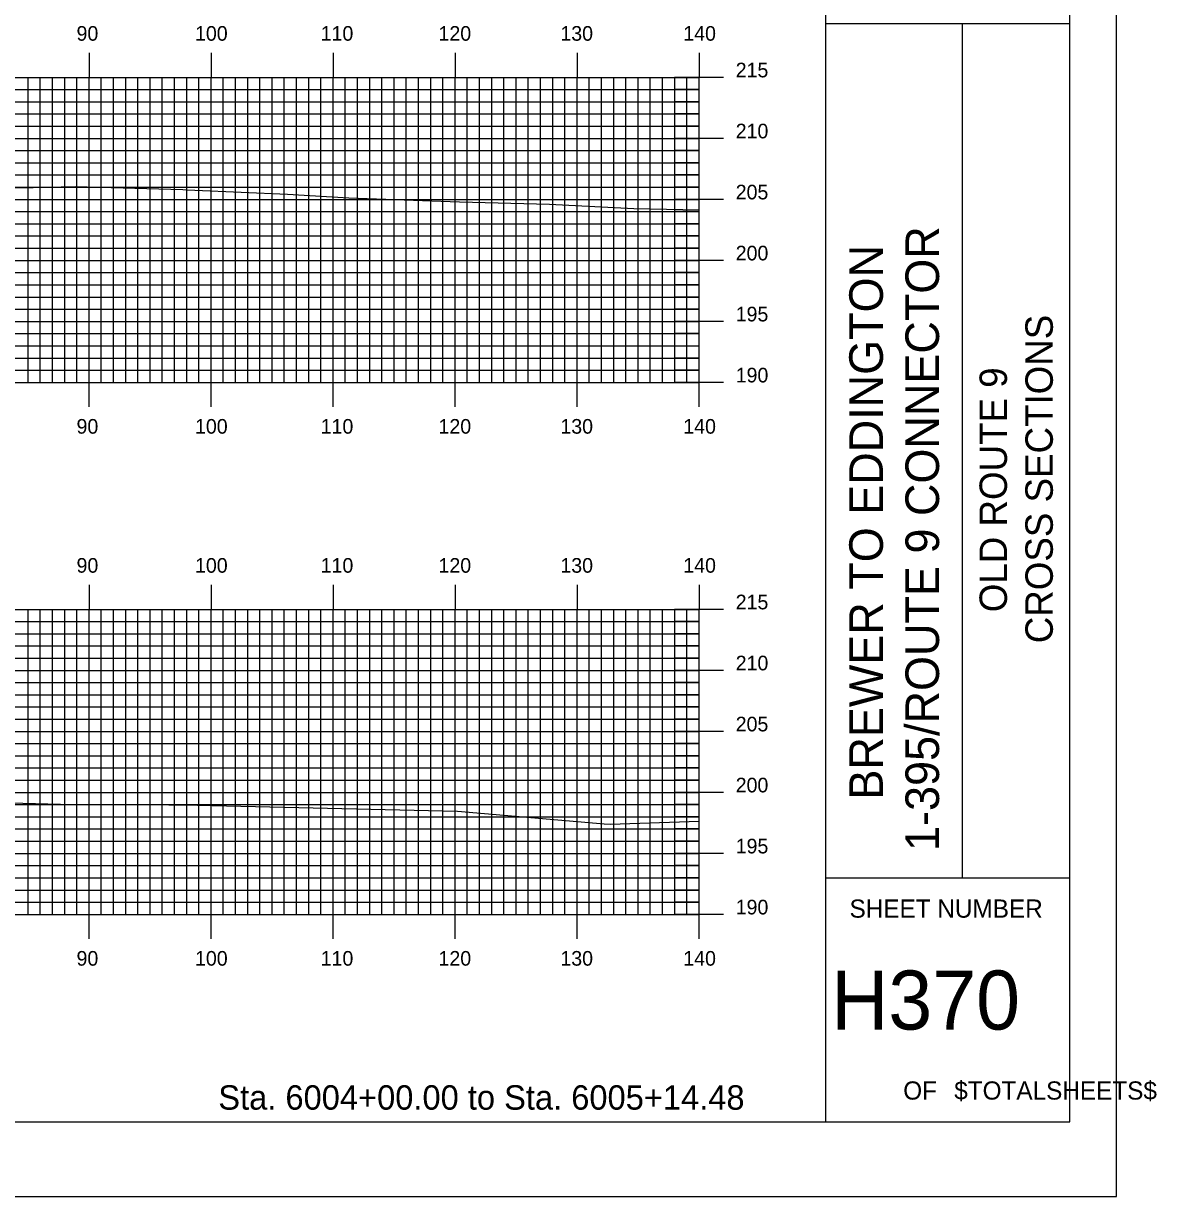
# Model space of a CAD drawing. Extents: x 852087 to 852430, y 366898 to 367118.
# Drawn here: x 852337.2 to 852430, y 366898.4 to 366994.5 of the extents above; entities that cross this region are included whole.
import ezdxf

# ---------------------------------------------------------------- set-up
doc = ezdxf.new("R2010")
doc.units = 0
for name, color, linetype in [('BORDER', 7, 'Continuous'), ('H_V ANNOTATION', 7, 'Continuous'), ('MAJOR', 7, 'Continuous'), ('MINOR', 7, 'Continuous'), ('PLOT BOUNDARY', 7, 'Continuous'), ('S_Roadway_Centerline', 7, 'Continuous')]:
    doc.layers.add(name, color=color, linetype=linetype)

msp = doc.modelspace()

# ---------------------------------------------------------------- linework, layer by layer
at = {"layer": 'BORDER'}
for p, q in [((852402.931, 366904.473), (852402.931, 367114.473)), ((852402.931, 366994.479), (852422.931, 366994.479)), ((852414.113, 366924.479), (852414.113, 366994.479)), ((852402.931, 366924.479), (852422.931, 366924.479))]:
    msp.add_line(p, q, dxfattribs=at)
msp.add_lwpolyline([(852102.931, 366904.473), (852422.931, 366904.473), (852422.931, 367114.473), (852102.931, 367114.473)], close=True, dxfattribs=at)
at = {"layer": 'MAJOR'}
for p, q in [((852342.531, 366992.071), (852342.531, 366990.067)), ((852352.531, 366992.071), (852352.531, 366990.067)), ((852362.531, 366992.071), (852362.531, 366990.067)), ((852372.531, 366992.071), (852372.531, 366990.067)), ((852382.531, 366992.071), (852382.531, 366990.067)), ((852392.531, 366992.071), (852392.531, 366990.067)), ((852112.531, 366990.067), (852392.531, 366990.067)), ((852112.531, 366990.067), (852392.531, 366990.067)), ((852342.531, 366965.067), (852342.531, 366990.067)), ((852352.531, 366965.067), (852352.531, 366990.067)), ((852362.531, 366965.067), (852362.531, 366990.067)), ((852372.531, 366965.067), (852372.531, 366990.067)), ((852382.531, 366965.067), (852382.531, 366990.067)), ((852394.535, 366990.067), (852390.527, 366990.067)), ((852392.531, 366965.067), (852392.531, 366990.067)), ((852392.531, 366965.067), (852392.531, 366990.067)), ((852112.531, 366985.067), (852392.531, 366985.067)), ((852394.535, 366985.067), (852390.527, 366985.067)), ((852112.531, 366980.067), (852392.531, 366980.067)), ((852394.535, 366980.067), (852390.527, 366980.067)), ((852112.531, 366975.067), (852392.531, 366975.067)), ((852394.535, 366975.067), (852390.527, 366975.067)), ((852112.531, 366970.067), (852392.531, 366970.067)), ((852394.535, 366970.067), (852390.527, 366970.067)), ((852112.531, 366965.067), (852392.531, 366965.067)), ((852112.531, 366965.067), (852392.531, 366965.067)), ((852342.531, 366963.063), (852342.531, 366965.067)), ((852352.531, 366963.063), (852352.531, 366965.067)), ((852362.531, 366963.063), (852362.531, 366965.067)), ((852372.531, 366963.063), (852372.531, 366965.067)), ((852382.531, 366963.063), (852382.531, 366965.067)), ((852394.535, 366965.067), (852390.527, 366965.067)), ((852392.531, 366963.063), (852392.531, 366965.067)), ((852342.531, 366948.477), (852342.531, 366946.473)), ((852352.531, 366948.477), (852352.531, 366946.473)), ((852362.531, 366948.477), (852362.531, 366946.473)), ((852372.531, 366948.477), (852372.531, 366946.473)), ((852382.531, 366948.477), (852382.531, 366946.473)), ((852392.531, 366948.477), (852392.531, 366946.473)), ((852112.531, 366946.473), (852392.531, 366946.473)), ((852112.531, 366946.473), (852392.531, 366946.473)), ((852342.531, 366921.473), (852342.531, 366946.473)), ((852352.531, 366921.473), (852352.531, 366946.473)), ((852362.531, 366921.473), (852362.531, 366946.473)), ((852372.531, 366921.473), (852372.531, 366946.473)), ((852382.531, 366921.473), (852382.531, 366946.473)), ((852394.535, 366946.473), (852390.527, 366946.473)), ((852392.531, 366921.473), (852392.531, 366946.473)), ((852392.531, 366921.473), (852392.531, 366946.473)), ((852112.531, 366941.473), (852392.531, 366941.473)), ((852394.535, 366941.473), (852390.527, 366941.473)), ((852112.531, 366936.473), (852392.531, 366936.473)), ((852394.535, 366936.473), (852390.527, 366936.473)), ((852112.531, 366931.473), (852392.531, 366931.473)), ((852394.535, 366931.473), (852390.527, 366931.473)), ((852112.531, 366926.473), (852392.531, 366926.473)), ((852394.535, 366926.473), (852390.527, 366926.473)), ((852112.531, 366921.473), (852392.531, 366921.473)), ((852112.531, 366921.473), (852392.531, 366921.473)), ((852342.531, 366919.469), (852342.531, 366921.473)), ((852352.531, 366919.469), (852352.531, 366921.473)), ((852362.531, 366919.469), (852362.531, 366921.473)), ((852372.531, 366919.469), (852372.531, 366921.473)), ((852382.531, 366919.469), (852382.531, 366921.473)), ((852394.535, 366921.473), (852390.527, 366921.473)), ((852392.531, 366919.469), (852392.531, 366921.473))]:
    msp.add_line(p, q, dxfattribs=at)
at = {"layer": 'MINOR'}
for p, q in [((852337.531, 366965.067), (852337.531, 366990.067)), ((852338.531, 366965.067), (852338.531, 366990.067)), ((852339.531, 366965.067), (852339.531, 366990.067)), ((852340.531, 366965.067), (852340.531, 366990.067)), ((852341.531, 366965.067), (852341.531, 366990.067)), ((852343.531, 366965.067), (852343.531, 366990.067)), ((852344.531, 366965.067), (852344.531, 366990.067)), ((852345.531, 366965.067), (852345.531, 366990.067)), ((852346.531, 366965.067), (852346.531, 366990.067)), ((852347.531, 366965.067), (852347.531, 366990.067)), ((852348.531, 366965.067), (852348.531, 366990.067)), ((852349.531, 366965.067), (852349.531, 366990.067)), ((852350.531, 366965.067), (852350.531, 366990.067)), ((852351.531, 366965.067), (852351.531, 366990.067)), ((852353.531, 366965.067), (852353.531, 366990.067)), ((852354.531, 366965.067), (852354.531, 366990.067)), ((852355.531, 366965.067), (852355.531, 366990.067)), ((852356.531, 366965.067), (852356.531, 366990.067)), ((852357.531, 366965.067), (852357.531, 366990.067)), ((852358.531, 366965.067), (852358.531, 366990.067)), ((852359.531, 366965.067), (852359.531, 366990.067)), ((852360.531, 366965.067), (852360.531, 366990.067)), ((852361.531, 366965.067), (852361.531, 366990.067)), ((852363.531, 366965.067), (852363.531, 366990.067)), ((852364.531, 366965.067), (852364.531, 366990.067)), ((852365.531, 366965.067), (852365.531, 366990.067)), ((852366.531, 366965.067), (852366.531, 366990.067)), ((852367.531, 366965.067), (852367.531, 366990.067)), ((852368.531, 366965.067), (852368.531, 366990.067)), ((852369.531, 366965.067), (852369.531, 366990.067)), ((852370.531, 366965.067), (852370.531, 366990.067)), ((852371.531, 366965.067), (852371.531, 366990.067)), ((852373.531, 366965.067), (852373.531, 366990.067)), ((852374.531, 366965.067), (852374.531, 366990.067)), ((852375.531, 366965.067), (852375.531, 366990.067)), ((852376.531, 366965.067), (852376.531, 366990.067)), ((852377.531, 366965.067), (852377.531, 366990.067)), ((852378.531, 366965.067), (852378.531, 366990.067)), ((852379.531, 366965.067), (852379.531, 366990.067)), ((852380.531, 366965.067), (852380.531, 366990.067)), ((852381.531, 366965.067), (852381.531, 366990.067)), ((852383.531, 366965.067), (852383.531, 366990.067)), ((852384.531, 366965.067), (852384.531, 366990.067)), ((852385.531, 366965.067), (852385.531, 366990.067)), ((852386.531, 366965.067), (852386.531, 366990.067)), ((852387.531, 366965.067), (852387.531, 366990.067)), ((852388.531, 366965.067), (852388.531, 366990.067)), ((852389.531, 366965.067), (852389.531, 366990.067)), ((852390.531, 366965.067), (852390.531, 366990.067)), ((852391.531, 366965.067), (852391.531, 366990.067)), ((852112.531, 366989.067), (852392.531, 366989.067)), ((852392.531, 366989.067), (852390.527, 366989.067)), ((852112.531, 366988.067), (852392.531, 366988.067)), ((852392.531, 366988.067), (852390.527, 366988.067)), ((852112.531, 366987.067), (852392.531, 366987.067)), ((852392.531, 366987.067), (852390.527, 366987.067)), ((852112.531, 366986.067), (852392.531, 366986.067)), ((852392.531, 366986.067), (852390.527, 366986.067)), ((852112.531, 366984.067), (852392.531, 366984.067)), ((852392.531, 366984.067), (852390.527, 366984.067)), ((852112.531, 366983.067), (852392.531, 366983.067)), ((852392.531, 366983.067), (852390.527, 366983.067)), ((852112.531, 366982.067), (852392.531, 366982.067)), ((852392.531, 366982.067), (852390.527, 366982.067)), ((852112.531, 366981.067), (852392.531, 366981.067)), ((852392.531, 366981.067), (852390.527, 366981.067)), ((852112.531, 366979.067), (852392.531, 366979.067)), ((852392.531, 366979.067), (852390.527, 366979.067)), ((852112.531, 366978.067), (852392.531, 366978.067)), ((852392.531, 366978.067), (852390.527, 366978.067)), ((852112.531, 366977.067), (852392.531, 366977.067)), ((852392.531, 366977.067), (852390.527, 366977.067)), ((852112.531, 366976.067), (852392.531, 366976.067)), ((852392.531, 366976.067), (852390.527, 366976.067)), ((852112.531, 366974.067), (852392.531, 366974.067)), ((852392.531, 366974.067), (852390.527, 366974.067)), ((852112.531, 366973.067), (852392.531, 366973.067)), ((852392.531, 366973.067), (852390.527, 366973.067)), ((852112.531, 366972.067), (852392.531, 366972.067)), ((852392.531, 366972.067), (852390.527, 366972.067)), ((852112.531, 366971.067), (852392.531, 366971.067)), ((852392.531, 366971.067), (852390.527, 366971.067)), ((852112.531, 366969.067), (852392.531, 366969.067)), ((852392.531, 366969.067), (852390.527, 366969.067)), ((852112.531, 366968.067), (852392.531, 366968.067)), ((852112.531, 366967.067), (852392.531, 366967.067)), ((852392.531, 366967.067), (852390.527, 366967.067)), ((852112.531, 366966.067), (852392.531, 366966.067)), ((852392.531, 366966.067), (852390.527, 366966.067)), ((852337.531, 366921.473), (852337.531, 366946.473)), ((852338.531, 366921.473), (852338.531, 366946.473)), ((852339.531, 366921.473), (852339.531, 366946.473)), ((852340.531, 366921.473), (852340.531, 366946.473)), ((852341.531, 366921.473), (852341.531, 366946.473)), ((852343.531, 366921.473), (852343.531, 366946.473)), ((852344.531, 366921.473), (852344.531, 366946.473)), ((852345.531, 366921.473), (852345.531, 366946.473)), ((852346.531, 366921.473), (852346.531, 366946.473)), ((852347.531, 366921.473), (852347.531, 366946.473)), ((852348.531, 366921.473), (852348.531, 366946.473)), ((852349.531, 366921.473), (852349.531, 366946.473)), ((852350.531, 366921.473), (852350.531, 366946.473)), ((852351.531, 366921.473), (852351.531, 366946.473)), ((852353.531, 366921.473), (852353.531, 366946.473)), ((852354.531, 366921.473), (852354.531, 366946.473)), ((852355.531, 366921.473), (852355.531, 366946.473)), ((852356.531, 366921.473), (852356.531, 366946.473)), ((852357.531, 366921.473), (852357.531, 366946.473)), ((852358.531, 366921.473), (852358.531, 366946.473)), ((852359.531, 366921.473), (852359.531, 366946.473)), ((852360.531, 366921.473), (852360.531, 366946.473)), ((852361.531, 366921.473), (852361.531, 366946.473)), ((852363.531, 366921.473), (852363.531, 366946.473)), ((852364.531, 366921.473), (852364.531, 366946.473)), ((852365.531, 366921.473), (852365.531, 366946.473)), ((852366.531, 366921.473), (852366.531, 366946.473)), ((852367.531, 366921.473), (852367.531, 366946.473)), ((852368.531, 366921.473), (852368.531, 366946.473)), ((852369.531, 366921.473), (852369.531, 366946.473)), ((852370.531, 366921.473), (852370.531, 366946.473)), ((852371.531, 366921.473), (852371.531, 366946.473)), ((852373.531, 366921.473), (852373.531, 366946.473)), ((852374.531, 366921.473), (852374.531, 366946.473)), ((852375.531, 366921.473), (852375.531, 366946.473)), ((852376.531, 366921.473), (852376.531, 366946.473)), ((852377.531, 366921.473), (852377.531, 366946.473)), ((852378.531, 366921.473), (852378.531, 366946.473)), ((852379.531, 366921.473), (852379.531, 366946.473)), ((852380.531, 366921.473), (852380.531, 366946.473)), ((852381.531, 366921.473), (852381.531, 366946.473)), ((852383.531, 366921.473), (852383.531, 366946.473)), ((852384.531, 366921.473), (852384.531, 366946.473)), ((852385.531, 366921.473), (852385.531, 366946.473)), ((852386.531, 366921.473), (852386.531, 366946.473)), ((852387.531, 366921.473), (852387.531, 366946.473)), ((852388.531, 366921.473), (852388.531, 366946.473)), ((852389.531, 366921.473), (852389.531, 366946.473)), ((852390.531, 366921.473), (852390.531, 366946.473)), ((852391.531, 366921.473), (852391.531, 366946.473)), ((852112.531, 366945.473), (852392.531, 366945.473)), ((852392.531, 366945.473), (852390.527, 366945.473)), ((852112.531, 366944.473), (852392.531, 366944.473)), ((852392.531, 366944.473), (852390.527, 366944.473)), ((852112.531, 366943.473), (852392.531, 366943.473)), ((852392.531, 366943.473), (852390.527, 366943.473)), ((852112.531, 366942.473), (852392.531, 366942.473)), ((852392.531, 366942.473), (852390.527, 366942.473)), ((852112.531, 366940.473), (852392.531, 366940.473)), ((852392.531, 366940.473), (852390.527, 366940.473)), ((852112.531, 366939.473), (852392.531, 366939.473)), ((852392.531, 366939.473), (852390.527, 366939.473)), ((852112.531, 366938.473), (852392.531, 366938.473)), ((852392.531, 366938.473), (852390.527, 366938.473)), ((852112.531, 366937.473), (852392.531, 366937.473)), ((852392.531, 366937.473), (852390.527, 366937.473)), ((852112.531, 366935.473), (852392.531, 366935.473)), ((852392.531, 366935.473), (852390.527, 366935.473)), ((852112.531, 366934.473), (852392.531, 366934.473)), ((852392.531, 366934.473), (852390.527, 366934.473)), ((852112.531, 366933.473), (852392.531, 366933.473)), ((852392.531, 366933.473), (852390.527, 366933.473)), ((852112.531, 366932.473), (852392.531, 366932.473)), ((852392.531, 366932.473), (852390.527, 366932.473)), ((852112.531, 366930.473), (852392.531, 366930.473)), ((852392.531, 366930.473), (852390.527, 366930.473)), ((852112.531, 366929.473), (852392.531, 366929.473)), ((852392.531, 366929.473), (852390.527, 366929.473)), ((852112.531, 366928.473), (852392.531, 366928.473)), ((852392.531, 366928.473), (852390.527, 366928.473)), ((852112.531, 366927.473), (852392.531, 366927.473)), ((852392.531, 366927.473), (852390.527, 366927.473)), ((852112.531, 366925.473), (852392.531, 366925.473)), ((852392.531, 366925.473), (852390.527, 366925.473)), ((852112.531, 366924.473), (852392.531, 366924.473)), ((852392.531, 366924.473), (852390.527, 366924.473)), ((852112.531, 366923.473), (852392.531, 366923.473)), ((852392.531, 366923.473), (852390.527, 366923.473)), ((852112.531, 366922.473), (852392.531, 366922.473)), ((852392.531, 366922.473), (852390.527, 366922.473))]:
    msp.add_line(p, q, dxfattribs=at)
at = {"layer": 'PLOT BOUNDARY'}
msp.add_lwpolyline([(852086.744, 366898.355), (852426.744, 366898.355), (852426.744, 367118.355), (852086.744, 367118.355)], close=True, dxfattribs=at)
at = {"layer": 'S_Roadway_Centerline'}
for points in [[(852336.05, 366981.045), (852337.951, 366981.036), (852341.38, 366981.112), (852350.218, 366980.865), (852350.566, 366980.857), (852351.195, 366980.833), (852358.792, 366980.493), (852363.834, 366980.203), (852372.902, 366979.868), (852380.266, 366979.668), (852387.189, 366979.306), (852392.531, 366979.212)], [(852336.074, 366930.619), (852341.222, 366930.486), (852347.841, 366930.486), (852349.068, 366930.462), (852350.236, 366930.451), (852372.73, 366929.931), (852384.739, 366928.899), (852385.237, 366928.867), (852392.531, 366929.112)]]:
    msp.add_lwpolyline(points, dxfattribs=at)

# ---------------------------------------------------------------- texts
at = {"layer": 'BORDER'}
for s, height, p in [('1-395/ROUTE 9 CONNECTOR', 2.75575, (852412.201, 366926.673)), ('BREWER TO EDDINGTON', 2.75575, (852407.599, 366930.882)), ('CROSS SECTIONS', 2.25, (852421.526, 366943.695)), ('OLD ROUTE 9', 2.25, (852417.768, 366946.237))]:
    msp.add_text(s, height=height, rotation=90, dxfattribs=at).set_placement(p)
for s, height, p in [('SHEET NUMBER', 1.49054, (852404.862, 366921.206)), ('H370', 4.8388, (852403.37, 366912.038)), ('$TOTALSHEETS$', 1.49054, (852413.444, 366906.299)), ('OF', 1.4905, (852409.265, 366906.299))]:
    msp.add_text(s, height=height, dxfattribs=at).set_placement(p)
at = {"layer": 'H_V ANNOTATION'}
for s, height, p in [('90', 1.2, (852341.503, 366993.067)), ('100', 1.2, (852351.214, 366993.067)), ('110', 1.2, (852361.514, 366993.067)), ('120', 1.2, (852371.172, 366993.067)), ('130', 1.2, (852381.161, 366993.067)), ('140', 1.2, (852391.236, 366993.067)), ('215', 1.2, (852395.531, 366990.067)), ('210', 1.2, (852395.531, 366985.067)), ('205', 1.2, (852395.531, 366980.067)), ('200', 1.2, (852395.531, 366975.067)), ('195', 1.2, (852395.531, 366970.067)), ('190', 1.2, (852395.531, 366965.067)), ('90', 1.2, (852341.503, 366960.867)), ('100', 1.2, (852351.214, 366960.867)), ('110', 1.2, (852361.514, 366960.867)), ('120', 1.2, (852371.172, 366960.867)), ('130', 1.2, (852381.161, 366960.867)), ('140', 1.2, (852391.236, 366960.867)), ('90', 1.2, (852341.503, 366949.473)), ('100', 1.2, (852351.214, 366949.473)), ('110', 1.2, (852361.514, 366949.473)), ('120', 1.2, (852371.172, 366949.473)), ('130', 1.2, (852381.161, 366949.473)), ('140', 1.2, (852391.236, 366949.473)), ('215', 1.2, (852395.531, 366946.473)), ('210', 1.2, (852395.531, 366941.473)), ('205', 1.2, (852395.531, 366936.473)), ('200', 1.2, (852395.531, 366931.473)), ('195', 1.2, (852395.531, 366926.473)), ('190', 1.2, (852395.531, 366921.473)), ('90', 1.2, (852341.503, 366917.273)), ('100', 1.2, (852351.214, 366917.273)), ('110', 1.2, (852361.514, 366917.273)), ('120', 1.2, (852371.172, 366917.273)), ('130', 1.2, (852381.161, 366917.273)), ('140', 1.2, (852391.236, 366917.273)), ('Sta. 6004+00.00 to Sta. 6005+14.48', 2.0004, (852353.124, 366905.473))]:
    msp.add_text(s, height=height, dxfattribs=at).set_placement(p)

doc.saveas('drawing.dxf')
